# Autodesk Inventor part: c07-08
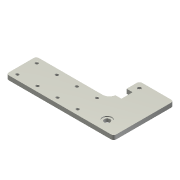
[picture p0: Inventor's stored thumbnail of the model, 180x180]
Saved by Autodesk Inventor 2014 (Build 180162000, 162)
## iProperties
Created: 2010-12
Part Number: c07-08
Material: Steel
Document SubType Name: Modeling
Designer: Beta-8540w
Mass: 1769.34 g
Surface Area: 558.866 cm^2
Volume: 225.394 cm^3
Density: 7.85 g/cm^3
Appearance: Smooth - Ivory
Author: Beta-8540w
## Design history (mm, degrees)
sketch "Sketch1"
  geometry: L1 (0, 0)-(250, 0); L2 (250, 0)-(250, 70); L3 (250, 70)-(0, 70); L4 (0, 70)-(0, 0); L5 (250, 70)-(170, 70); L6 (170, 70)-(170, 140); L7 (170, 140)-(250, 140); L8 (250, 140)-(250, 70)
  constraints: 16 end point, 4 parallel, 2 horizontal, 2 perpendicular
  dimensions: "d0" = 250 distance of L3.end L2.end; "d1" = 70 distance of L2.end L1.end; "d2" = 80 distance of L6.end L7.end; "d3" = 70 distance of L5.end L6.end
extrude "Extrusion1" new body sketch "Sketch1" distance "d4" = 10; taper "d5" = 0 deg
sketch "Sketch4"
  geometry: L1 (250, 140)-(170, 140) reference; L2 (170, 140)-(170, 70) reference; L3 (170, 84)-(184, 84); L4 (184, 84)-(184, 110); L5 (184, 110)-(170, 110); L6 (170, 110)-(170, 84)
  constraints: 8 end point, 2 parallel, 1 horizontal, 1 perpendicular, 1 point on line
  dimensions: "d41" = 14 distance of L5.end L4.end; "d42" = 26 distance of L4.end L3.end; "d43" = 30 distance between parallel lines of L1 L5
extrude "Extrusion2" cut sketch "Sketch4" stored distance "d44" = 10; taper "d45" = 0 deg
sketch "Sketch2"
  geometry: L1 (0, 70)-(0, 0) reference; L2 (14, 12.5)-(154, 12.5); L3 (154, 12.5)-(154, 57.5); L4 (154, 57.5)-(14, 57.5); L5 (14, 57.5)-(14, 12.5); L6 (60.667, 57.5)-(60.667, 12.5); L7 (107.333, 57.5)-(107.333, 12.5); 2 further points
  constraints: 12 end point, 4 point on line, 3 perpendicular, 2 midpoint, 2 parallel, 1 horizontal, 1 horizontal alignment
  dimensions: "d6" = 140 distance of L4.end L3.end; "d7" = 45 distance of L3.end L2.end; "d8" = 46.66667 distance between parallel lines of L6 L5 (= 0.333333 x d6); "d9" = 46.66667 distance between parallel lines of L7 L6 (= d8); "d10" = 14 distance between parallel lines of L1 L5
hole "Hole1" sketch "Sketch2" at (14, 12.5), (154, 57.5), (154, 12.5), (14, 57.5), (60.667, 57.5), (60.667, 12.5), (107.333, 57.5), (107.333, 12.5) diameter "d11" = 6.6; stored, may be unused: countersink angle "d15" = 90 deg, drill point angle "d17" = 118 deg; dims "d12" = 6, "d13" = 4, "d14" = 90, "d16" = 8
hole "Hole3" diameter "d52" = 3.242; stored, may be unused: countersink angle "d56" = 90 deg, drill point angle "d58" = 118 deg; dims "d50" = 43, "d51" = 5, "d53" = 8, "d54" = 4, "d55" = 2, "d57" = 10
fillet "Fillet1" dims "d39" = 6, "d46" = 1
fillet "Fillet2" dims "d40" = 16
chamfer "Chamfer1" distance "d47" = 0.5; stored, may be unused: second distance "d48" = 2, angle "d49" = 45 deg
chamfer "Chamfer2" distance "d59" = 0.5; stored, may be unused: second distance "d60" = 2, angle "d61" = 45 deg
hole "Hole6" diameter "d74" = 4.5; stored, may be unused: countersink angle "d78" = 90 deg, drill point angle "d80" = 118 deg; dims "d72" = 14, "d73" = 14, "d75" = 6, "d76" = 8, "d77" = 4, "d79" = 8
body "Solid1"
hole "Hole2" diameter "d32" = 13.492; stored, may be unused: countersink angle "d36" = 90 deg, drill point angle "d38" = 118 deg; dims "d30" = 40, "d31" = 25, "d33" = 6, "d34" = 22.225, "d35" = 2, "d37" = 8
